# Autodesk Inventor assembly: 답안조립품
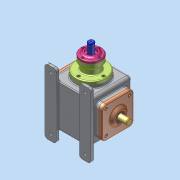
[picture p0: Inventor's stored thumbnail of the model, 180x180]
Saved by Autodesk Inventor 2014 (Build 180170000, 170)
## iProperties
Created: 2026-01
Part Number: 답안조립품
Document SubType Name: Assembly
Designer: dg
Author: dg
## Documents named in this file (16)
- C:\Users\dg\Desktop\760103V1011\답안조립품.iam
- C:\Users\dg\Desktop\760103V1011\본체.ipt
- C:\Users\dg\Desktop\760103V1011\가져온 구성요소\6각 구멍붙이 볼트 M4x10\6각 구멍붙이 볼트 M4x10.ipt
- C:\Users\dg\Desktop\760103V1011\가져온 구성요소\6각 구멍붙이 볼트 M6x12\6각 구멍붙이 볼트 M6x12.ipt
- C:\Users\dg\Desktop\760103V1011\가져온 구성요소\구동축\구동축.ipt
- C:\Users\dg\Desktop\760103V1011\가져온 구성요소\베벨 기어(구동)\베벨 기어(구동).ipt
- C:\Users\dg\Desktop\760103V1011\가져온 구성요소\베벨 기어(종동)\베벨 기어(종동).ipt
- C:\Users\dg\Desktop\760103V1011\가져온 구성요소\베어링 하우징\베어링 하우징.ipt
- C:\Users\dg\Desktop\760103V1011\가져온 구성요소\엔드캡\엔드캡.ipt
- C:\Users\dg\Desktop\760103V1011\가져온 구성요소\오일 실 20 35 8\오일 실 20 35 8.ipt
- C:\Users\dg\Desktop\760103V1011\가져온 구성요소\종동축\종동축.ipt
- C:\Users\dg\Desktop\760103V1011\가져온 구성요소\측면 커버\측면 커버.ipt
- C:\Users\dg\Desktop\760103V1011\가져온 구성요소\칼라\칼라.ipt
- C:\Users\dg\Desktop\760103V1011\가져온 구성요소\테이퍼 롤러 베어링 30204K\테이퍼 롤러 베어링 30204K.ipt
- C:\Users\dg\Desktop\760103V1011\가져온 구성요소\평행 키 6x6x18\평행 키 6x6x18.ipt
- C:\Users\dg\Desktop\760103V1011\가져온 구성요소\하우징 커버\하우징 커버.ipt
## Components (19 placed, 4 different names)
1. 6각 구멍붙이 볼트 M6x12:1
2. 구동축:1
3. 하우징 커버:1
4. 6각 구멍붙이 볼트 M6x12:6
5. 6각 구멍붙이 볼트 M6x12:7
6. 6각 구멍붙이 볼트 M6x12:8
7. 6각 구멍붙이 볼트 M6x12:9
8. 6각 구멍붙이 볼트 M6x12:10
9. 6각 구멍붙이 볼트 M6x12:11
10. 6각 구멍붙이 볼트 M6x12:12
11. 6각 구멍붙이 볼트 M6x12:13
12. 6각 구멍붙이 볼트 M6x12:2
13. 6각 구멍붙이 볼트 M6x12:3
14. 6각 구멍붙이 볼트 M6x12:4
15. 6각 구멍붙이 볼트 M6x12:5
16. 6각 구멍붙이 볼트 M4x10:1
17. 6각 구멍붙이 볼트 M4x10:2
18. 6각 구멍붙이 볼트 M4x10:3
19. 6각 구멍붙이 볼트 M4x10:4
